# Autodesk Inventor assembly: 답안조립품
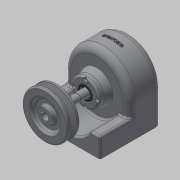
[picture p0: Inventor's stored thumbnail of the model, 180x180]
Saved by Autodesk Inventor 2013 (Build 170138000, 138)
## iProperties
Created: 2015-02
Part Number: 답안조립품
Document SubType Name: Assembly
Designer: Administrator
Author: Administrator
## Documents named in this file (10)
- C:\Users\Administrator\Desktop\450216V1019\답안조립품.iam
- C:\Users\Administrator\Desktop\450216V1019\본체.ipt
- C:\Users\Administrator\Desktop\450216V1019\축커버.ipt
- C:\Users\Administrator\Desktop\450216V1019\축.ipt
- C:\Users\Administrator\Desktop\450216V1019\베어링 6001.ipt
- C:\Users\Administrator\Desktop\450216V1019\키5x5.ipt
- C:\Users\Administrator\Desktop\450216V1019\키4x4.ipt
- C:\Users\Administrator\Desktop\450216V1019\오일실.ipt
- C:\Users\Administrator\Desktop\450216V1019\스퍼기어.ipt
- C:\Users\Administrator\Desktop\450216V1019\V-벨트풀리.ipt
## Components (1 placed, 1 different names)
1. V-벨트풀리:1
